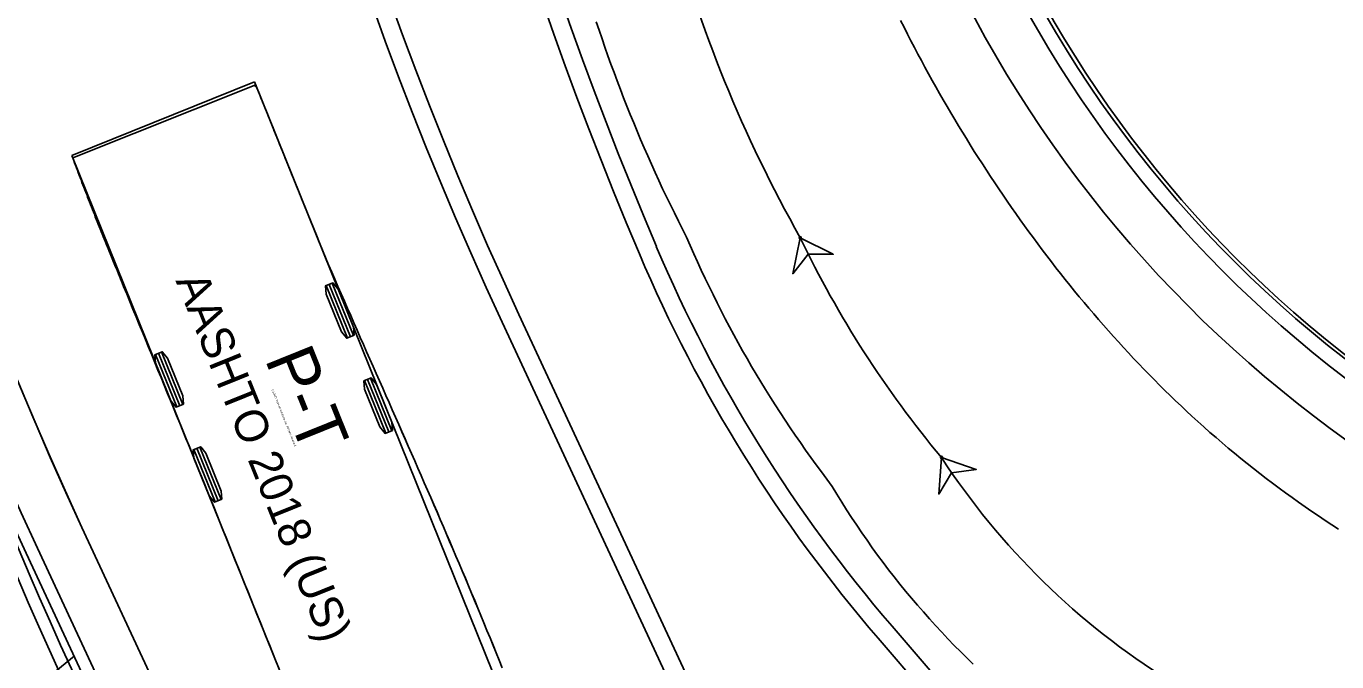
# Model space of a CAD drawing. Extents: x -14 to 1565148, y -25 to 642856.
# Drawn here: x 1564741.9 to 1564795.2, y 636567.8 to 636593.6 of the extents above; entities that cross this region are included whole.
import ezdxf

# ---------------------------------------------------------------- set-up
doc = ezdxf.new("R2010")
doc.units = 0
for name, color, linetype in [('DR_P_Drainage_Area', 7, 'Continuous'), ('DR_P_Erosion_Control', 7, 'Continuous'), ('DR_P_Headwall', 7, 'Continuous'), ('GE_X_Alignment', 7, 'Continuous'), ('PV_P_Drive', 7, 'Continuous'), ('PV_P_EOP', 7, 'Continuous'), ('PV_X_COP', 7, 'Continuous'), ('PV_X_EOP', 7, 'Continuous')]:
    doc.layers.add(name, color=color, linetype=linetype)

msp = doc.modelspace()

# ---------------------------------------------------------------- linework, layer by layer
at = {"layer": 'DR_P_Drainage_Area'}
for radius in [162.5, 162]:
    msp.add_arc((1564891.023, 636634.993), radius, 162.35779, 209.87935, dxfattribs=at)
at = {"layer": 'DR_P_Erosion_Control'}
msp.add_line((1564754.742, 636550.56), (1564744.193, 636573.226), dxfattribs=at)
msp.add_arc((1564880.185, 636636.521), 150, 165.19841, 204.95884, dxfattribs=at)
at = {"layer": 'DR_P_Headwall'}
for p, q in [((1564751.205, 636591.331), (1564743.786, 636588.337)), ((1564761.308, 636566.292), (1564751.205, 636591.331)), ((1564743.786, 636588.337), (1564753.889, 636563.299)), ((1564754.984, 636580.922), (1564754.123, 636583.055)), ((1564755.104, 636580.97), (1564754.244, 636583.103)), ((1564755.225, 636581.019), (1564754.365, 636583.152)), ((1564748.048, 636578.123), (1564747.187, 636580.256)), ((1564748.169, 636578.172), (1564747.308, 636580.305)), ((1564748.289, 636578.221), (1564747.429, 636580.354)), ((1564756.543, 636577.058), (1564755.682, 636579.191)), ((1564756.664, 636577.107), (1564755.803, 636579.239)), ((1564756.784, 636577.155), (1564755.924, 636579.288)), ((1564749.607, 636574.259), (1564748.746, 636576.392)), ((1564749.728, 636574.308), (1564748.867, 636576.441)), ((1564749.848, 636574.357), (1564748.988, 636576.49))]:
    msp.add_line(p, q, dxfattribs=at)
for points in [[(1564776.98, 636571.507), (1564776.755, 636571.802), (1564776.534, 636572.1), (1564776.316, 636572.401), (1564776.101, 636572.703), (1564775.889, 636573.008), (1564775.681, 636573.316), (1564775.476, 636573.626), (1564775.274, 636573.938), (1564775.075, 636574.252), (1564774.88, 636574.569), (1564774.683, 636574.883), (1564774.471, 636575.184), (1564774.25, 636575.478), (1564774.032, 636575.774), (1564773.816, 636576.071), (1564773.603, 636576.37), (1564773.392, 636576.671), (1564773.183, 636576.974), (1564772.977, 636577.278), (1564772.773, 636577.584), (1564772.571, 636577.891), (1564772.372, 636578.2), (1564772.175, 636578.511), (1564771.98, 636578.823), (1564771.788, 636579.137), (1564771.599, 636579.452), (1564771.412, 636579.769), (1564771.227, 636580.087), (1564771.045, 636580.407), (1564770.866, 636580.728), (1564770.689, 636581.05), (1564770.514, 636581.374), (1564770.342, 636581.7), (1564770.173, 636582.027), (1564770.006, 636582.355), (1564769.842, 636582.684), (1564769.68, 636583.015), (1564769.521, 636583.347), (1564769.365, 636583.68), (1564769.211, 636584.014), (1564769.06, 636584.35), (1564768.911, 636584.686), (1564768.759, 636585.02), (1564768.597, 636585.349), (1564768.433, 636585.675), (1564768.271, 636586.003), (1564768.11, 636586.331), (1564767.952, 636586.661), (1564767.795, 636586.991), (1564767.641, 636587.322), (1564767.489, 636587.655), (1564767.338, 636587.988), (1564767.19, 636588.322), (1564767.044, 636588.657), (1564766.899, 636588.993), (1564766.757, 636589.33), (1564766.617, 636589.667), (1564766.479, 636590.006), (1564766.343, 636590.345), (1564766.209, 636590.685), (1564766.077, 636591.026), (1564765.947, 636591.368), (1564765.82, 636591.71), (1564765.694, 636592.053), (1564765.57, 636592.397), (1564765.449, 636592.742), (1564765.33, 636593.087), (1564765.212, 636593.433), (1564765.097, 636593.779)], [(1564777.468, 636593.822), (1564777.605, 636593.55), (1564777.744, 636593.277), (1564777.884, 636593.006), (1564778.025, 636592.735), (1564778.168, 636592.465), (1564778.312, 636592.196), (1564778.457, 636591.927), (1564778.603, 636591.659), (1564778.751, 636591.392), (1564778.899, 636591.126), (1564779.05, 636590.861), (1564779.201, 636590.596), (1564779.354, 636590.332), (1564779.508, 636590.069), (1564779.664, 636589.807), (1564779.821, 636589.546), (1564779.979, 636589.286), (1564780.139, 636589.026), (1564780.299, 636588.767), (1564780.461, 636588.509), (1564780.625, 636588.252), (1564780.789, 636587.996), (1564780.955, 636587.741), (1564781.122, 636587.487), (1564781.29, 636587.233), (1564781.46, 636586.98), (1564781.631, 636586.728), (1564781.803, 636586.478), (1564781.976, 636586.228), (1564782.15, 636585.979), (1564782.326, 636585.73), (1564782.504, 636585.483), (1564782.682, 636585.237), (1564782.862, 636584.992), (1564783.043, 636584.748), (1564783.225, 636584.505), (1564783.409, 636584.263), (1564783.594, 636584.022), (1564783.78, 636583.781), (1564783.967, 636583.542), (1564784.156, 636583.304), (1564784.346, 636583.067), (1564784.538, 636582.832), (1564784.73, 636582.597), (1564784.925, 636582.363), (1564785.12, 636582.131), (1564785.317, 636581.9), (1564785.515, 636581.67), (1564785.714, 636581.441), (1564785.915, 636581.213), (1564786.117, 636580.986), (1564786.32, 636580.761), (1564786.525, 636580.537), (1564786.731, 636580.314), (1564786.938, 636580.093), (1564787.147, 636579.873), (1564787.357, 636579.654), (1564787.568, 636579.436), (1564787.781, 636579.22), (1564787.995, 636579.005), (1564788.21, 636578.792), (1564788.427, 636578.58), (1564788.645, 636578.37), (1564788.865, 636578.161), (1564789.086, 636577.953), (1564789.308, 636577.747), (1564789.551, 636577.526), (1564789.795, 636577.306), (1564790.04, 636577.088), (1564790.288, 636576.872), (1564790.537, 636576.658), (1564790.787, 636576.446), (1564791.039, 636576.236), (1564791.293, 636576.029), (1564791.549, 636575.823), (1564791.805, 636575.619), (1564792.064, 636575.417), (1564792.324, 636575.217), (1564792.585, 636575.02), (1564792.847, 636574.824), (1564793.111, 636574.63), (1564793.376, 636574.438), (1564793.643, 636574.249), (1564793.91, 636574.061), (1564794.179, 636573.876), (1564794.449, 636573.692), (1564794.721, 636573.511), (1564794.993, 636573.332), (1564795.267, 636573.155)], [(1564752.19, 636567.51), (1564752.063, 636567.823), (1564751.937, 636568.137), (1564751.811, 636568.45), (1564751.684, 636568.763), (1564751.558, 636569.075), (1564751.432, 636569.388), (1564751.306, 636569.701), (1564751.18, 636570.013), (1564751.054, 636570.325), (1564750.928, 636570.637), (1564750.802, 636570.949), (1564750.676, 636571.261), (1564750.551, 636571.572), (1564750.425, 636571.884), (1564750.299, 636572.195), (1564750.174, 636572.506), (1564750.048, 636572.817), (1564749.923, 636573.128), (1564749.798, 636573.439), (1564749.672, 636573.749), (1564749.547, 636574.059), (1564749.422, 636574.369), (1564749.297, 636574.679), (1564749.172, 636574.989), (1564749.047, 636575.299), (1564748.922, 636575.609), (1564748.797, 636575.918), (1564748.671, 636576.227), (1564748.545, 636576.536), (1564748.419, 636576.844), (1564748.292, 636577.152), (1564748.166, 636577.461), (1564748.039, 636577.769), (1564747.913, 636578.078), (1564747.786, 636578.386), (1564747.66, 636578.694), (1564747.533, 636579.003), (1564747.407, 636579.312), (1564747.281, 636579.62), (1564747.154, 636579.929), (1564747.027, 636580.237), (1564746.901, 636580.546), (1564746.774, 636580.856), (1564746.647, 636581.165), (1564746.52, 636581.474), (1564746.394, 636581.783), (1564746.267, 636582.092), (1564746.14, 636582.402), (1564746.013, 636582.711), (1564745.886, 636583.02), (1564745.844, 636583.124), (1564745.802, 636583.227), (1564745.76, 636583.33), (1564745.718, 636583.433), (1564745.676, 636583.537), (1564745.633, 636583.64), (1564745.591, 636583.743), (1564745.548, 636583.846), (1564745.506, 636583.949), (1564745.463, 636584.052), (1564745.421, 636584.155), (1564745.339, 636584.355), (1564745.298, 636584.455), (1564745.257, 636584.555), (1564745.216, 636584.655), (1564745.176, 636584.755), (1564745.135, 636584.855), (1564745.095, 636584.955), (1564745.054, 636585.054), (1564745.014, 636585.154), (1564744.974, 636585.254), (1564744.934, 636585.354), (1564744.894, 636585.454), (1564744.854, 636585.553), (1564744.814, 636585.653), (1564744.775, 636585.753), (1564744.735, 636585.852), (1564744.696, 636585.952), (1564744.657, 636586.052), (1564744.617, 636586.151), (1564744.578, 636586.251), (1564744.539, 636586.351), (1564744.5, 636586.45), (1564744.462, 636586.55), (1564744.423, 636586.65), (1564744.385, 636586.749), (1564744.346, 636586.849), (1564744.308, 636586.948), (1564744.27, 636587.048), (1564744.232, 636587.147), (1564744.194, 636587.247), (1564744.156, 636587.346), (1564744.118, 636587.446), (1564744.081, 636587.545), (1564744.043, 636587.644), (1564744.006, 636587.744), (1564743.969, 636587.843), (1564743.932, 636587.943), (1564743.895, 636588.042), (1564743.858, 636588.141), (1564743.822, 636588.241), (1564751.253, 636591.212)], [(1564751.684, 636568.763), (1564751.558, 636569.075), (1564751.432, 636569.388), (1564751.306, 636569.701), (1564751.18, 636570.013), (1564751.054, 636570.325), (1564750.928, 636570.637), (1564750.802, 636570.949), (1564750.676, 636571.261), (1564750.551, 636571.573), (1564750.425, 636571.884), (1564750.299, 636572.195), (1564750.174, 636572.506), (1564750.048, 636572.817), (1564749.923, 636573.128), (1564749.798, 636573.439), (1564749.672, 636573.749), (1564749.547, 636574.059), (1564749.422, 636574.37), (1564749.297, 636574.68), (1564749.172, 636574.989), (1564749.047, 636575.299), (1564748.922, 636575.609), (1564748.797, 636575.918), (1564748.671, 636576.227), (1564748.545, 636576.536), (1564748.419, 636576.844), (1564748.292, 636577.153), (1564748.166, 636577.461), (1564748.039, 636577.769), (1564747.913, 636578.078), (1564747.786, 636578.386), (1564747.66, 636578.694), (1564747.533, 636579.003), (1564747.407, 636579.312), (1564747.281, 636579.62), (1564747.154, 636579.929), (1564747.027, 636580.237), (1564746.901, 636580.546), (1564746.774, 636580.856), (1564746.647, 636581.164), (1564746.52, 636581.473), (1564746.394, 636581.783), (1564746.267, 636582.092), (1564746.14, 636582.402), (1564746.013, 636582.711), (1564745.886, 636583.02), (1564745.844, 636583.123), (1564745.802, 636583.227), (1564745.76, 636583.33), (1564745.718, 636583.433), (1564745.676, 636583.536), (1564745.633, 636583.64), (1564745.591, 636583.743), (1564745.548, 636583.846), (1564745.506, 636583.949), (1564745.463, 636584.052), (1564745.421, 636584.155), (1564745.339, 636584.355), (1564745.298, 636584.455), (1564745.257, 636584.555), (1564745.216, 636584.655), (1564745.176, 636584.755), (1564745.135, 636584.855), (1564745.095, 636584.955), (1564745.054, 636585.054), (1564745.014, 636585.154), (1564744.974, 636585.254), (1564744.934, 636585.354), (1564744.894, 636585.454), (1564744.854, 636585.553), (1564744.814, 636585.653), (1564744.775, 636585.753), (1564744.735, 636585.852), (1564744.696, 636585.952), (1564744.657, 636586.052), (1564744.617, 636586.151), (1564744.578, 636586.251), (1564744.539, 636586.351), (1564744.5, 636586.45), (1564744.462, 636586.55), (1564744.423, 636586.65), (1564744.385, 636586.749), (1564744.346, 636586.849), (1564744.308, 636586.948), (1564744.27, 636587.048), (1564744.232, 636587.147), (1564744.194, 636587.247), (1564744.156, 636587.346), (1564744.118, 636587.446), (1564744.081, 636587.545), (1564744.043, 636587.644), (1564744.006, 636587.744), (1564743.969, 636587.843), (1564743.932, 636587.943), (1564743.895, 636588.042), (1564743.858, 636588.141), (1564743.822, 636588.241), (1564751.198, 636591.19)], [(1564751.198, 636591.19), (1564751.283, 636591.129), (1564751.319, 636591.049), (1564751.352, 636590.967), (1564751.384, 636590.886), (1564751.417, 636590.804), (1564751.45, 636590.723), (1564751.483, 636590.641), (1564751.516, 636590.56), (1564751.549, 636590.478), (1564751.582, 636590.397), (1564751.615, 636590.315), (1564751.648, 636590.233), (1564751.681, 636590.152), (1564751.714, 636590.07), (1564751.746, 636589.989), (1564751.779, 636589.907), (1564751.812, 636589.825), (1564751.845, 636589.744), (1564751.878, 636589.662), (1564751.911, 636589.58), (1564751.944, 636589.499), (1564751.977, 636589.417), (1564752.01, 636589.335), (1564752.043, 636589.254), (1564752.076, 636589.172), (1564752.109, 636589.09), (1564752.142, 636589.008), (1564752.175, 636588.927), (1564752.208, 636588.845), (1564752.241, 636588.763), (1564752.274, 636588.682), (1564752.307, 636588.6), (1564752.34, 636588.518), (1564752.373, 636588.436), (1564752.406, 636588.354), (1564752.439, 636588.273), (1564752.472, 636588.191), (1564752.505, 636588.109), (1564752.538, 636588.027), (1564752.571, 636587.946), (1564752.604, 636587.864), (1564752.67, 636587.7), (1564752.71, 636587.6), (1564752.751, 636587.5), (1564752.791, 636587.399), (1564752.832, 636587.299), (1564752.872, 636587.199), (1564752.912, 636587.099), (1564752.953, 636586.999), (1564752.993, 636586.899), (1564753.034, 636586.799), (1564753.074, 636586.698), (1564753.114, 636586.598), (1564753.236, 636586.298), (1564753.357, 636585.997), (1564753.478, 636585.697), (1564753.599, 636585.397), (1564753.72, 636585.097), (1564753.842, 636584.796), (1564753.963, 636584.497), (1564754.086, 636584.198), (1564754.213, 636583.901), (1564754.341, 636583.605), (1564754.47, 636583.309), (1564754.598, 636583.013), (1564754.727, 636582.718), (1564754.856, 636582.423), (1564754.985, 636582.127), (1564755.115, 636581.833), (1564755.244, 636581.538), (1564755.374, 636581.243), (1564755.504, 636580.949), (1564755.634, 636580.654), (1564755.764, 636580.36), (1564755.894, 636580.065), (1564756.024, 636579.771), (1564756.154, 636579.476), (1564756.284, 636579.181), (1564756.415, 636578.887), (1564756.545, 636578.592), (1564756.675, 636578.297), (1564756.806, 636578.002), (1564756.936, 636577.707), (1564757.066, 636577.411), (1564757.197, 636577.116), (1564757.327, 636576.82), (1564757.457, 636576.524), (1564757.587, 636576.228), (1564757.717, 636575.932), (1564757.847, 636575.635), (1564757.977, 636575.338), (1564758.107, 636575.041), (1564758.236, 636574.744), (1564758.366, 636574.446), (1564758.495, 636574.149), (1564758.624, 636573.851), (1564758.753, 636573.552), (1564758.881, 636573.254), (1564759.01, 636572.955), (1564759.138, 636572.656), (1564759.266, 636572.356), (1564759.394, 636572.056), (1564759.521, 636571.756), (1564759.648, 636571.456), (1564759.775, 636571.155), (1564759.902, 636570.854), (1564760.028, 636570.553), (1564760.154, 636570.251), (1564760.279, 636569.949), (1564760.405, 636569.647), (1564760.529, 636569.344), (1564760.654, 636569.041), (1564760.778, 636568.738), (1564760.901, 636568.435), (1564761.025, 636568.131), (1564761.147, 636567.827), (1564761.27, 636567.523)], [(1564751.253, 636591.212), (1564751.286, 636591.131), (1564751.319, 636591.049), (1564751.351, 636590.968), (1564751.384, 636590.886), (1564751.417, 636590.805), (1564751.45, 636590.723), (1564751.483, 636590.641), (1564751.516, 636590.56), (1564751.549, 636590.478), (1564751.582, 636590.397), (1564751.615, 636590.315), (1564751.648, 636590.233), (1564751.681, 636590.152), (1564751.714, 636590.07), (1564751.746, 636589.989), (1564751.779, 636589.907), (1564751.812, 636589.825), (1564751.845, 636589.744), (1564751.878, 636589.662), (1564751.911, 636589.58), (1564751.944, 636589.499), (1564751.977, 636589.417), (1564752.01, 636589.335), (1564752.043, 636589.254), (1564752.076, 636589.172), (1564752.109, 636589.09), (1564752.142, 636589.008), (1564752.175, 636588.927), (1564752.208, 636588.845), (1564752.241, 636588.763), (1564752.274, 636588.681), (1564752.307, 636588.6), (1564752.34, 636588.518), (1564752.373, 636588.436), (1564752.406, 636588.354), (1564752.439, 636588.272), (1564752.472, 636588.191), (1564752.505, 636588.109), (1564752.538, 636588.027), (1564752.571, 636587.945), (1564752.604, 636587.863), (1564752.67, 636587.7), (1564752.71, 636587.6), (1564752.751, 636587.499), (1564752.791, 636587.399), (1564752.832, 636587.299), (1564752.872, 636587.199), (1564752.913, 636587.098), (1564752.953, 636586.998), (1564752.993, 636586.898), (1564753.034, 636586.798), (1564753.074, 636586.698), (1564753.115, 636586.598), (1564753.236, 636586.297), (1564753.357, 636585.997), (1564753.478, 636585.696), (1564753.6, 636585.396), (1564753.721, 636585.096), (1564753.842, 636584.796), (1564753.963, 636584.495), (1564754.086, 636584.196), (1564754.214, 636583.9), (1564754.342, 636583.604), (1564754.47, 636583.308), (1564754.599, 636583.012), (1564754.728, 636582.716), (1564754.857, 636582.421), (1564754.986, 636582.126), (1564755.115, 636581.831), (1564755.245, 636581.536), (1564755.375, 636581.241), (1564755.504, 636580.947), (1564755.634, 636580.652), (1564755.764, 636580.358), (1564755.894, 636580.063), (1564756.025, 636579.769), (1564756.155, 636579.474), (1564756.285, 636579.179), (1564756.416, 636578.884), (1564756.546, 636578.59), (1564756.676, 636578.295), (1564756.807, 636578), (1564756.937, 636577.704), (1564757.067, 636577.409), (1564757.198, 636577.113), (1564757.328, 636576.817), (1564757.458, 636576.521), (1564757.588, 636576.225), (1564757.718, 636575.929), (1564757.848, 636575.632), (1564757.978, 636575.335), (1564758.108, 636575.038), (1564758.237, 636574.741), (1564758.367, 636574.443), (1564758.496, 636574.146), (1564758.625, 636573.848), (1564758.754, 636573.549), (1564758.883, 636573.251), (1564759.011, 636572.952), (1564759.139, 636572.652), (1564759.267, 636572.353), (1564759.395, 636572.053), (1564759.522, 636571.753), (1564759.65, 636571.453), (1564759.777, 636571.152), (1564759.903, 636570.851), (1564760.029, 636570.549), (1564760.155, 636570.248), (1564760.281, 636569.946), (1564760.406, 636569.643), (1564760.531, 636569.341), (1564760.655, 636569.038), (1564760.779, 636568.735), (1564760.903, 636568.431), (1564761.026, 636568.128), (1564761.149, 636567.824), (1564761.271, 636567.52)], [(1564773.387, 636585), (1564773.083, 636583.531), (1564773.713, 636584.325), (1564774.727, 636584.326), (1564773.387, 636585)], [(1564779.125, 636576.072), (1564779.018, 636574.576), (1564779.538, 636575.446), (1564780.542, 636575.582), (1564779.125, 636576.072)], [(1564780.413, 636567.672), (1564780.172, 636567.906), (1564779.909, 636568.166), (1564779.649, 636568.43), (1564779.392, 636568.696), (1564779.137, 636568.965), (1564778.886, 636569.236), (1564778.637, 636569.511), (1564778.391, 636569.788), (1564778.149, 636570.068), (1564777.909, 636570.351), (1564777.672, 636570.636), (1564777.438, 636570.924), (1564777.207, 636571.214), (1564776.98, 636571.507)], [(1564752.19, 636567.51), (1564752.064, 636567.823), (1564751.937, 636568.136), (1564751.811, 636568.45), (1564751.684, 636568.763)]]:
    msp.add_lwpolyline(points, dxfattribs=at)
for points in [[(1564773.387, 636585), (1564773.083, 636583.531), (1564773.713, 636584.325), (1564774.727, 636584.326)], [(1564755.255, 636581.031), (1564754.954, 636580.91), (1564754.742, 636581.172), (1564754.123, 636582.707), (1564754.093, 636583.043), (1564754.395, 636583.164), (1564754.606, 636582.902), (1564755.225, 636581.367)], [(1564748.319, 636578.233), (1564748.018, 636578.111), (1564747.807, 636578.373), (1564747.187, 636579.909), (1564747.157, 636580.244), (1564747.459, 636580.366), (1564747.67, 636580.104), (1564748.29, 636578.568)], [(1564756.814, 636577.167), (1564756.513, 636577.046), (1564756.302, 636577.308), (1564755.682, 636578.843), (1564755.652, 636579.179), (1564755.954, 636579.3), (1564756.165, 636579.038), (1564756.785, 636577.503)], [(1564749.878, 636574.369), (1564749.577, 636574.247), (1564749.366, 636574.509), (1564748.746, 636576.045), (1564748.716, 636576.38), (1564749.018, 636576.502), (1564749.229, 636576.24), (1564749.849, 636574.704)], [(1564779.125, 636576.072), (1564779.018, 636574.576), (1564779.538, 636575.446), (1564780.542, 636575.582)]]:
    msp.add_lwpolyline(points, close=True, dxfattribs=at)
for centre in [(1564773.387, 636585), (1564773.387, 636585), (1564779.125, 636576.072), (1564779.125, 636576.072)]:
    msp.add_circle(centre, 0.0417, dxfattribs=at)
for centre, radius, start, end in [((1564822.406, 636612.605), 56.257, 194.9833, 209.3861), ((1564811.85, 636603.41), 42.642, 205.5781, 219.8751), ((1564804.256, 636592.456), 30, 213.1018, 238.0724)]:
    msp.add_arc(centre, radius, start, end, dxfattribs=at)
at = {"layer": 'GE_X_Alignment'}
for p, q in [((1564772.648, 636558.894), (1564761.951, 636581.877)), ((1564776.549, 636568.723), (1564786.898, 636556.685))]:
    msp.add_line(p, q, dxfattribs=at)
for centre, radius, start, end in [((1564896.356, 636644.434), 148.25, 167.11776, 204.95884), ((1564915.759, 636647.501), 161.75, 172.10361, 202.98217), ((1564824.56, 636617.524), 47.25, 198.1955, 261.3289), ((1564821.855, 636607.676), 59.75, 202.98217, 220.68817)]:
    msp.add_arc(centre, radius, start, end, dxfattribs=at)
at = {"layer": 'PV_P_Drive'}
msp.add_arc((1564824.589, 636617.648), 47.5, 198.1955, 264.1817, dxfattribs=at)
at = {"layer": 'PV_P_EOP'}
for p, q in [((1564772.648, 636558.894), (1564761.951, 636581.877)), ((1564771.968, 636558.578), (1564761.271, 636581.56)), ((1564752.476, 636549.505), (1564741.927, 636572.171)), ((1564752.929, 636549.716), (1564742.38, 636572.382)), ((1564787.467, 636557.174), (1564777.118, 636569.212)), ((1564786.898, 636556.685), (1564776.549, 636568.723))]:
    msp.add_line(p, q, dxfattribs=at)
for centre, radius, start, end in [((1564896.356, 636644.434), 149, 167.11776, 204.95884), ((1564896.356, 636644.434), 148.25, 167.11776, 204.95884), ((1564880.185, 636636.521), 152.5, 167.11776, 204.95884), ((1564880.185, 636636.521), 152, 167.11776, 204.95884), ((1564915.759, 636647.501), 161.75, 172.10361, 202.98217), ((1564915.759, 636647.501), 161, 172.10361, 202.98217), ((1564824.56, 636617.524), 48, 198.1955, 261.3289), ((1564824.56, 636617.524), 47.25, 198.1955, 261.3289), ((1564821.855, 636607.676), 59, 202.98217, 220.68817), ((1564821.855, 636607.676), 59.75, 202.98217, 220.68817)]:
    msp.add_arc(centre, radius, start, end, dxfattribs=at)
at = {"layer": 'PV_X_COP'}
msp.add_line((1564739.066, 636564.098), (1564743.872, 636567.99), dxfattribs=at)
at = {"layer": 'PV_X_EOP'}
msp.add_line((1564754.742, 636550.56), (1564744.193, 636573.226), dxfattribs=at)
for centre, radius, start, end in [((1564880.185, 636636.521), 150, 167.11776, 204.95884), ((1564824.56, 636617.524), 50, 198.1955, 261.3289)]:
    msp.add_arc(centre, radius, start, end, dxfattribs=at)

# ---------------------------------------------------------------- texts
at = {"layer": 'DR_P_Headwall'}
for s, height, p in [('AASHTO 2018 (US)', 1.33333, (1564747.987, 636583.254)), ('P-T', 2, (1564751.609, 636580.068)), ('(c) 2021 Transoft Solutions, Inc. All rights reserved.', 0.08, (1564751.9, 636578.812))]:
    msp.add_text(s, height=height, rotation=291.974, dxfattribs=at).set_placement(p)

doc.saveas('drawing.dxf')
